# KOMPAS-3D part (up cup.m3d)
File: created 05.10.2016 12:06:01, last saved 05.10.2016 12:23:00.
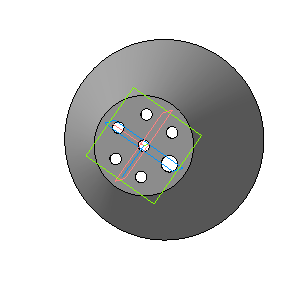
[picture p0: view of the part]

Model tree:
1. Эскиз:1
2. Операция вращения:1
     Угол 1 = 360
3. Эскиз:2
4. Вырезать элемент выдавливания:1
     Расстояние 1 = 10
